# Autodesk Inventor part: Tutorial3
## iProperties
Created: 2009-03
Part Number: Tutorial3
Document SubType Name: Modeling
Designer: Sham
Density: 1 g/cm^3
Author: Sham
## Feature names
1. Extrusion1
2. Extrusion3
3. Hole1
4. Circular Pattern1
5. Extrusion4
6. Hole2
7. Circular Pattern2
8. Hole3
